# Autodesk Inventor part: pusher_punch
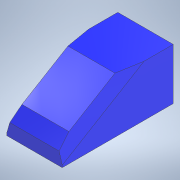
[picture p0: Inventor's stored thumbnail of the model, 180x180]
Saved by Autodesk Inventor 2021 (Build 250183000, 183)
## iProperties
Created: 2026-10
Part Number: pusher_punch
Material: Generic
Document SubType Name: Modeling
Designer: alolo
Density: 1 g/cm^3
Appearance: Default
Author: alolo
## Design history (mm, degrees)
sketch "Sketch1"
  geometry: L1 (0, 0)-(65, 0); L2 (65, 0)-(65, 80); L3 (65, 80)-(0, 80); L4 (0, 80)-(0, 0)
  constraints: 8 end point, 2 parallel, 1 horizontal, 1 perpendicular
  dimensions: "d0" = 65 distance of L3.end L2.end (= slide_width); "d1" = 80 distance of L2.end L1.end
extrude "Extrusion1" new body sketch "Sketch1" distance "d2" = 130; taper "d3" = 0 deg
sketch "Sketch2"
  geometry: L1 (0, 0)-(-65, 0) reference; L2 (-38.5, 0)-(-26.5, 0); L3 (-26.5, 0)-(-26.5, 15); L4 (-26.5, 15)-(-38.5, 15); L5 (-38.5, 15)-(-38.5, 0); 3 further points
  constraints: 8 end point, 2 midpoint, 2 parallel, 1 coincident, 1 horizontal, 1 perpendicular, 1 point on line
  dimensions: "d19" = 12 distance of L4.end L3.end; "d20" = 15 distance of L2.end L3.end
extrude "Extrusion2" cut sketch "Sketch2" distance "d21" = 40; taper "d22" = 0 deg
chamfer "Chamfer6" distance "d23" = 60; stored, may be unused: second distance "d24" = 100, angle "d25" = 45 deg
chamfer "Chamfer7" distance "d26" = 15; stored, may be unused: second distance "d27" = 5, angle "d28" = 45 deg
chamfer "Chamfer8" distance "d29" = 10; stored, may be unused: second distance "d30" = 2, angle "d31" = 45 deg
chamfer "Chamfer10" distance "d35" = 5; stored, may be unused: second distance "d36" = 15, angle "d37" = 45 deg
chamfer "Chamfer11" distance "d38" = 5; stored, may be unused: second distance "d39" = 15, angle "d40" = 45 deg
sketch "Sketch3"
  geometry: L1 (-65, 0)-(-65, 80) reference; L2 (0, 80)-(0, 0) reference; L3 (-65, 80)-(0, 80); L4 (0, 80)-(0, 60); L5 (0, 60)-(-65, 60); L6 (-65, 60)-(-65, 80); 2 further points
  constraints: 8 end point, 2 parallel, 1 horizontal, 1 perpendicular, 1 point on line
  dimensions: "d41" = 20 distance of L3.end L4.end
extrude "Extrusion3" cut sketch "Sketch3" stored distance "d42" = 10; taper "d43" = 0 deg
body "Solid1"
other parameters: "slide_length" = 195 [user parameter], "slide_angle" = 7 deg [user parameter], "slide_width" = 65 [user parameter; used in 1 equation term], "wood_thickness" = 5 [user parameter], "aclyric_thickness" = 6 [user parameter]
